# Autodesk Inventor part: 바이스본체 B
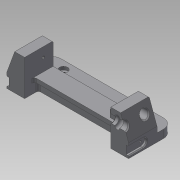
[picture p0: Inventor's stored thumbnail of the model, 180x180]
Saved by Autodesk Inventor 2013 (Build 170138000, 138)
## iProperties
Created: 2017-04
Part Number: 바이스본체 B
Material: 알루미늄 6061
Document SubType Name: Modeling
Designer: mduedu
Density: 2.71 g/cm^3
Mass: 324.158 g
Surface Area: 275.767 cm^2
Volume: 119.615 cm^3
Author: mduedu
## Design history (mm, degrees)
sketch "스케치1"
  geometry: L1 (-75, 0)-(75, 0); L2 (-75, 0)-(-75, 17); L3 (-53, 17)-(53, 17); L4 (75, 17)-(75, 0); L5 (-75, 17)-(-65.173, 44); L6 (-65.173, 44)-(-53, 44); L7 (-53, 44)-(-53, 17); L8 (0, 0)-(0, 17); L9 (75, 17)-(65.173, 44); L10 (65.173, 44)-(53, 44); L11 (53, 44)-(53, 17); 1 further point
  constraints: 22 end point, 4 perpendicular, 2 horizontal alignment, 2 midpoint, 2 symmetric about line, 1 coincident, 1 collinear, 1 horizontal, 1 vertical
  dimensions: "d0" = 150 distance of L1.start L1.end; "d1" = 17 distance of L1.start L2.end; "d2" = 27 distance of L3.start L6.end; "d3" = 22 distance of L3.start L2.end; "d4" = 70 deg angle of L3 L5; "d54" = 20 deg angle of L9 L4
extrude "돌출1" new body sketch "스케치1" stored distance "d5" = 70; taper "d6" = 0 deg
sketch "스케치2"
  geometry: L1 (0, 70)-(106, 70) reference; L2 (106, 70)-(106, 0) reference; L3 (106, 0)-(0, 0) reference; L4 (0, 47)-(106, 47); L5 (106, 47)-(106, 23); L6 (106, 23)-(0, 23); L7 (0, 23)-(0, 47); L8 (0, 70)-(0, 0) reference; 2 further points
  constraints: 8 end point, 2 parallel, 2 point on line, 1 horizontal, 1 horizontal alignment, 1 midpoint, 1 perpendicular
  dimensions: "d7" = 24 distance between parallel lines of L6 L4
extrude "돌출2" cut sketch "스케치2" stored distance "d9" = 70; taper "d10" = 0 deg
sketch "스케치3"
  geometry: L1 (22, -23)-(128, -23) reference; L2 (128, -47)-(22, -47) reference; L3 (22, -18)-(128, -18); L4 (128, -52)-(22, -52); L5 (22, -18)-(22, -52); L6 (128, -18)-(128, -52); 1 further point
  constraints: 8 end point, 3 parallel, 2 point on line, 1 perpendicular
  dimensions: "d11" = 5 distance between parallel lines of L3 L1; "d12" = 5 distance between parallel lines of L4 L2
extrude "돌출3" cut sketch "스케치3" distance "d13" = 12; taper "d14" = 0 deg
fillet "모깎기1" dims "d15" = 3, "d16" = 3
sketch "스케치4"
  geometry: L1 (103, 23)-(3, 23) reference; L2 (0, 26)-(0, 0) reference; L3 (106, 0)-(0, 0) reference; L4 (106, 26)-(106, 0) reference; L5 (96, 0)-(90, 0); L6 (90, 0)-(90, 19.5); L7 (96, 19.5)-(96, 0); L8 (90, 19.5)-(96, 19.5); A1 r 3 centre (3, 26) between (0, 26) and (3, 23) reference; A2 r 3 centre (103, 26) between (103, 23) and (106, 26) reference; 1 further point
  constraints: 8 end point, 2 perpendicular, 1 horizontal, 1 parallel, 1 point on line
  dimensions: "d17" = 10 distance between parallel lines of L7 L4; "d18" = 6 distance between parallel lines of L7 L6; "d27" = 3.5 distance between parallel lines of L8 L1
extrude "돌출4" join sketch "스케치4" distance "d19" = 12; taper "d20" = 0 deg
chamfer "모따기1" distance "d21" = 3; stored, may be unused: second distance "d22" = 2, angle "d23" = 45 deg
chamfer "모따기2" distance "d24" = 3; stored, may be unused: second distance "d25" = 2, angle "d26" = 45 deg
sketch "스케치5"
  geometry: L1 (-15.5, 35.8)-(-15.5, -25.8) reference; L2 (19.5, 0)-(0, 0) reference; C1 r 6.5 at (9.5, 15); 1 further point
  constraints: 1 centre point
  dimensions: "d28" = 13 diameter of C1; "d30" = 15 distance from line of C1.centre L2; "d31" = 25 distance from line of C1.centre L1
extrude "돌출5" cut sketch "스케치5" stored distance "d32" = 12; taper "d33" = 0 deg
sketch "스케치6"
  geometry: C1 r 5 at (-10, 15); C2 r 5 at (-60, 15); A1 r 6.5 centre (-10, 15) between (-15.766, 12) and (-4.234, 12) reference; A2 r 6.5 centre (-60, 15) between (-65.766, 12) and (-54.234, 12) reference; 1 further point
  constraints: 2 centre point, 2 coincident
  dimensions: "d34" = 10 diameter of C1; "d35" = 10 diameter of C2 (= d34)
extrude "돌출6" cut sketch "스케치6" stored distance "d36" = 12; taper "d37" = 0 deg
chamfer "모따기3" distance "d38" = 1; stored, may be unused: second distance "d39" = 2, angle "d40" = 45 deg
chamfer "모따기4" distance "d41" = 1; stored, may be unused: second distance "d42" = 2, angle "d43" = 45 deg
sketch "스케치7"
  geometry: L1 (-35, 35.8)-(-35, -25.8) reference; L2 (-70, 0)-(0, 0) reference; C1 r 5 at (-35, 15); 1 further point
  constraints: 1 centre point, 1 point on line
  dimensions: "d44" = 10 diameter of C1; "d45" = 15 distance from line of C1.centre L2
extrude "돌출7" cut sketch "스케치7" stored distance "d46" = 12; taper "d47" = 0 deg
chamfer "모따기5" distance "d48" = 1; stored, may be unused: second distance "d49" = 2, angle "d50" = 45 deg
node "작업축1"
sketch "스케치8"
  geometry: L1 (-105, 32)-(105, 32) reference; L2 (58, 32)-(64, 32); L3 (64, 32)-(64, 40); L4 (64, 40)-(58, 40); L5 (58, 40)-(58, 32); L6 (53, 38)-(53, 26) reference; 1 further point
  constraints: 8 end point, 2 parallel, 1 horizontal, 1 perpendicular, 1 point on line
  dimensions: "d51" = 5 distance from line of L6 L2.start; "d52" = 6 distance of L3.end L4.end; "d53" = 16 diameter of L4 L1
revolve "회전1" sketch "스케치8" stored, may be unused: angle "d55" = 90 deg
fillet "모깎기2"
chamfer "모따기6" distance "d56" = 1; stored, may be unused: second distance "d57" = 2, angle "d58" = 45 deg
sketch "스케치9"
  geometry: L1 (17.5, 3)-(52.5, 3); L2 (52.5, 13)-(17.5, 13); L3 (70, 0)-(0, 0) reference; L4 (17.5, 8)-(52.5, 8); A1 r 5 centre (17.5, 8) between (17.5, 13) and (17.5, 3); A2 r 5 centre (52.5, 8) between (52.5, 3) and (52.5, 13); 3 further points
  constraints: 6 end point, 4 point on circle, 3 tangent, 2 centre point, 2 midpoint, 2 parallel, 1 horizontal, 1 vertical alignment
  dimensions: "d59" = 35 distance of L4.start L4.end; "d61" = 5 radius of A2; "d62" = 8 distance between parallel lines of L3 L4
extrude "돌출8" cut sketch "스케치9" distance "d63" = 3; taper "d64" = 0 deg
chamfer "모따기7" distance "d65" = 1; stored, may be unused: second distance "d66" = 2, angle "d67" = 45 deg
chamfer "모따기8" distance "d68" = 1; stored, may be unused: second distance "d69" = 2, angle "d70" = 45 deg
feature "분할1"
sketch "스케치10"
  geometry: A1 r 5 centre (0, 0) between (0, 5) and (0, -5) reference; 1 further point
  constraints: 1 coincident
hole "구멍1" sketch "스케치10" at (0, 0) diameter "d71" = 2.459; stored, may be unused: countersink angle "d75" = 90 deg, drill point angle "d77" = 120 deg; dims "d72" = 4.5, "d73" = 4, "d74" = 2, "d76" = 6
sketch "스케치11"
  geometry: L1 (0, 0)-(0, 27) reference; L2 (0, 27)-(-35, 27) reference; 2 further points
  dimensions: "d78" = 12 distance from line of point (-12, 15.5) L1; "d79" = 11.5 distance from line of point (-12, 15.5) L2
hole "구멍2" sketch "스케치11" at (-12, 15.5) diameter "d80" = 3.242; stored, may be unused: countersink angle "d84" = 90 deg, drill point angle "d86" = 120 deg; dims "d81" = 6, "d82" = 4, "d83" = 2, "d85" = 8
sketch "스케치12"
  geometry: L1 (-75, -35)-(-75, 0) reference; L2 (75, -35)-(75, 0) reference; L3 (75, -35)-(-75, -35); L4 (-75, -35)-(-75, -55); L5 (-75, -55)-(75, -55); L6 (75, -55)-(75, -35); 1 further point
  constraints: 8 end point, 2 parallel, 1 horizontal, 1 perpendicular, 1 point on line
  dimensions: "d87" = 20 distance of L3.end L4.end; "d89" = 150 distance of L4.end L5.end (derived)
extrude "돌출9" join sketch "스케치12" distance "d90" = 10; taper "d91" = 0 deg
sketch "스케치13"
  geometry: L1 (-75, 55)-(-75, 35) reference; L2 (75, 35)-(75, 55) reference; L3 (-75, 45)-(75, 45); 3 further points
  constraints: 2 end point, 2 midpoint, 2 point on line
  dimensions: "d92" = 50 horizontal distance of point (-50, 45) point (0, 0); "d93" = 100 distance of point (50, 45) point (-50, 45)
fillet "모깎기3" dims "d94" = 12
chamfer "모따기9" distance "d95" = 1; stored, may be unused: second distance "d96" = 2, angle "d97" = 45 deg
hole "구멍3" sketch "스케치13" diameter "d98" = 4.134; stored, may be unused: countersink angle "d102" = 90 deg, drill point angle "d104" = 118 deg; dims "d99" = 6, "d100" = 10, "d101" = 4, "d103" = 8
node "솔리드1"
mirror "대칭1"
mirror "대칭2"
mirror "대칭3"
mirror "대칭4"
node "투영된 루프1"
